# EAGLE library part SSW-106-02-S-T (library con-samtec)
THROUGH-HOLE .025" SQ POST SOCKET Source: Samtec SSW.pdf
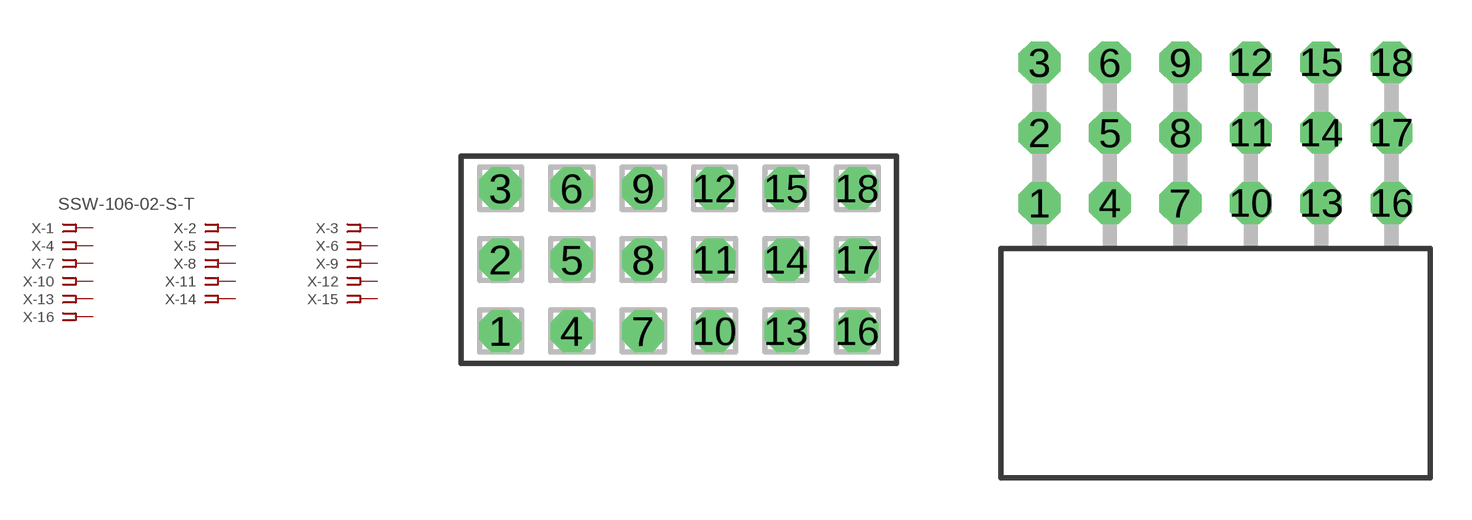
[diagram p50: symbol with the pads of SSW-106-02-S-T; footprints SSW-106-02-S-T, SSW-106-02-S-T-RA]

Designator prefix X; gates -1=FPINV -2=FPIN -3=FPIN -4=FPIN -5=FPIN -6=FPIN -7=FPIN -8=FPIN -9=FPIN -10=FPIN -11=FPIN -12=FPIN -13=FPIN -14=FPIN -15=FPIN -16=FPIN -17=FPIN -18=FPIN

## SSW-106-02-S-T (MPN: SSW-106-02-S-T; OC_FARNELL: unknown; OC_NEWARK: 82P3414)  [SSW-106-02-S-T]
1  -1:1  pas
2  -2:1  pas
3  -3:1  pas
4  -4:1  pas
5  -5:1  pas
6  -6:1  pas
7  -7:1  pas
8  -8:1  pas
9  -9:1  pas
10  -10:1  pas
11  -11:1  pas
12  -12:1  pas
13  -13:1  pas
14  -14:1  pas
15  -15:1  pas
16  -16:1  pas
17  -17:1  pas
18  -18:1  pas

## SSW-106-02-S-TRA (MPN: SSW-106-02-S-T-RA; OC_FARNELL: unknown; OC_NEWARK: 82P3415)  [SSW-106-02-S-T-RA]
Pads as for SSW-106-02-S-T

## Footprint SSW-106-02-S-T (pad centres in mm)
THROUGH-HOLE .025" SQ POST SOCKET Source: Samtec SSW.pdf
drill 1 pad 1.5 octagon: 1 -6.35,-2.54; 2 -6.35,0; 3 -6.35,2.54; 4 -3.81,-2.54; 5 -3.81,0; 6 -3.81,2.54; 7 -1.27,-2.54; 8 -1.27,0; 9 -1.27,2.54; 10 1.27,-2.54; 11 1.27,0; 12 1.27,2.54; 13 3.81,-2.54; 14 3.81,0; 15 3.81,2.54; 16 6.35,-2.54; 17 6.35,0; 18 6.35,2.54

## Footprint SSW-106-02-S-T-RA (pad centres in mm)
THROUGH-HOLE .025" SQ POST SOCKET Source: Samtec SSW.pdf
drill 1 pad 1.5 octagon: 1 -6.35,1.524; 2 -6.35,4.064; 3 -6.35,6.604; 4 -3.81,1.524; 5 -3.81,4.064; 6 -3.81,6.604; 7 -1.27,1.524; 8 -1.27,4.064; 9 -1.27,6.604; 10 1.27,1.524; 11 1.27,4.064; 12 1.27,6.604; 13 3.81,1.524; 14 3.81,4.064; 15 3.81,6.604; 16 6.35,1.524; 17 6.35,4.064; 18 6.35,6.604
